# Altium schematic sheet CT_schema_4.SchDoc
size 205 x 173 mm
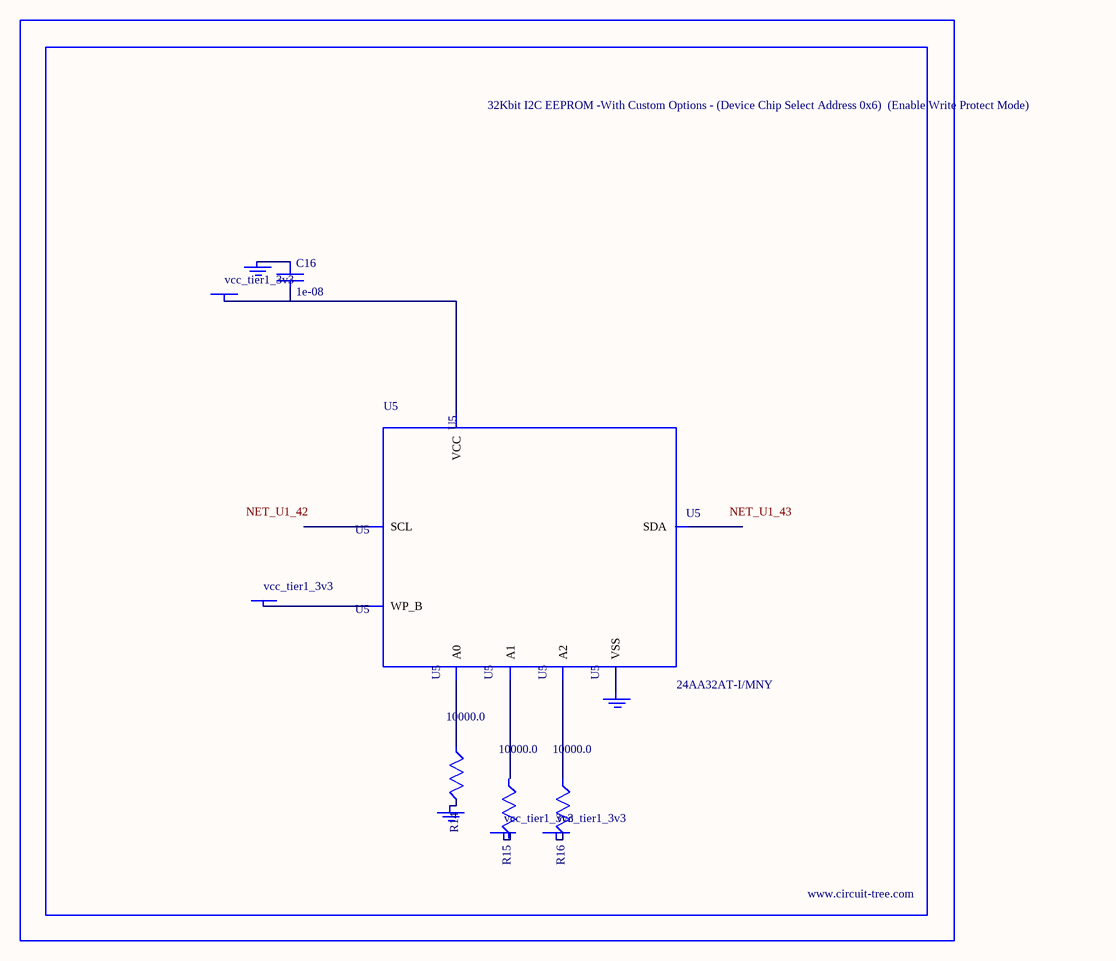
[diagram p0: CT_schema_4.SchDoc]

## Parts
BORDER3  (no value)
C16  1e-08  [C0402]
GND_INSTANCE_3_0  (no value)
GND_INSTANCE_3_1  (no value)
GND_INSTANCE_3_2  (no value)
POWER_INSTANCE_3_0  vcc_tier1_3v3
POWER_INSTANCE_3_1  vcc_tier1_3v3
POWER_INSTANCE_3_2  vcc_tier1_3v3
POWER_INSTANCE_3_3  vcc_tier1_3v3
R14  10000.0  [R0603]
R15  10000.0  [R0603]
R16  10000.0  [R0603]
U5  24AA32AT-I/MNY  [TDFN-8/6MM]

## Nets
NetC16_1: C16.1 GND_INSTANCE_3_1.0(GND)
NetC16_2: C16.2 POWER_INSTANCE_3_3.0(PWR) U5.8(VCC)
NetGND_INSTANCE_3_0_0: GND_INSTANCE_3_0.0(GND) R14.2
NetGND_INSTANCE_3_2_0: GND_INSTANCE_3_2.0(GND) U5.4(VSS)
NetPOWER_INSTANCE_3_1_0: POWER_INSTANCE_3_1.0(PWR) R16.2
NetPOWER_INSTANCE_3_2_0: POWER_INSTANCE_3_2.0(PWR) U5.7(WP_B)
NetR14_1: R14.1 U5.1(A0)
NetR16_1: R16.1 U5.3(A2)

Not connected (* = marked no-connect by the designer): POWER_INSTANCE_3_0 0(PWR); R15 1 2; U5 2(A1) 5(SDA) 6(SCL)

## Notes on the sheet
- Labels drawn without touching a wire or pin: NET_U1_42, NET_U1_43

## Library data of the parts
BORDER3 = BORDER_PAGE3
C16 = C0402C103K3RAC
GND_INSTANCE_3_0-GND_INSTANCE_3_2 = GND
POWER_INSTANCE_3_0-POWER_INSTANCE_3_3 = PWR
R14-R16 = RC0603JR-0710KL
